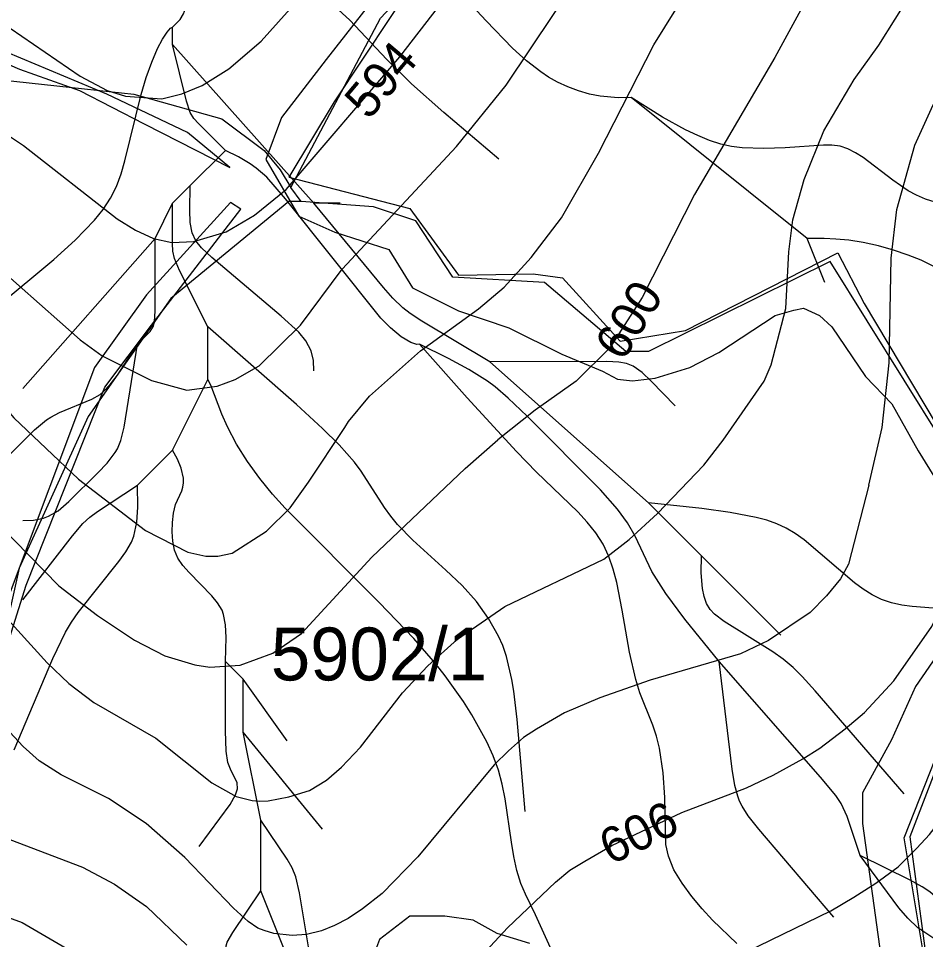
# Model space of a CAD drawing. Extents: x -709584 to -702006, y -1161789 to -1157496.
# Drawn here: x -705935.7 to -705678.4, y -1159835.9 to -1159574.6 of the extents above; entities that cross this region are included whole.
import ezdxf

# ---------------------------------------------------------------- set-up
doc = ezdxf.new("R2010")
doc.units = 0
for name, color, linetype in [('102_obvod PÚ', 7, 'Continuous'), ('120_vrstevnice hlavní', 7, 'Continuous'), ('121_vrstevnice hlavní_popis', 7, 'Continuous'), ('122_vrstevnice základní', 7, 'Continuous'), ('408_BPEJ_linie', 7, 'Continuous'), ('411_akumulovaný odtok', 7, 'Continuous'), ('419_LPIS PB', 7, 'Continuous'), ('419_LPIS PB_kod', 7, 'Continuous')]:
    doc.layers.add(name, color=color, linetype=linetype)

msp = doc.modelspace()

# ---------------------------------------------------------------- linework, layer by layer
at = {"layer": '102_obvod PÚ'}
msp.add_lwpolyline([(-705822.03, -1159561.79), (-705846.15, -1159598.18), (-705859.01, -1159619.55), (-705824.72, -1159628.51), (-705810.91, -1159647.42), (-705789.7, -1159647), (-705781.42, -1159648.14), (-705765.06, -1159666.07), (-705746.55, -1159663.11), (-705703.3, -1159641.06), (-705695.88, -1159655.44), (-705675.44, -1159689.62), (-705663.02, -1159711.13), (-705656.63, -1159738.39), (-705682.88, -1159806.7), (-705674.33, -1159870.62)], dxfattribs=at)
at = {"layer": '120_vrstevnice hlavní'}
for points in [[(-705524.12, -1159497.37), (-705538.14, -1159486.07), (-705565.6, -1159468.62), (-705579.33, -1159462.04), (-705588.48, -1159458.61), (-705602.78, -1159456.18), (-705618.23, -1159457.75), (-705633.24, -1159463.62), (-705642.4, -1159468.34), (-705650.83, -1159474.06), (-705658.41, -1159480.35), (-705665.14, -1159487.64), (-705675.43, -1159502.95), (-705684.16, -1159517.53), (-705721.2, -1159585.61), (-705743.94, -1159624.51), (-705758.81, -1159653.68), (-705767.96, -1159667.98), (-705777.54, -1159677.42), (-705789.16, -1159685.72), (-705799.75, -1159694.12)], [(-705977.91, -1159672.33), (-705972.26, -1159679.93), (-705953.66, -1159704.32), (-705945.4, -1159714.02), (-705924.31, -1159735.53), (-705913.33, -1159743.94), (-705902.79, -1159750.92), (-705894.24, -1159755.34), (-705885.69, -1159757.9), (-705881.42, -1159758.61), (-705872.87, -1159758.04), (-705863.6, -1159754.62), (-705855.48, -1159749.07), (-705835.53, -1159727.41), (-705809.03, -1159702.19), (-705799.75, -1159694.12)]]:
    msp.add_lwpolyline(points, dxfattribs=at)
msp.add_open_spline([(-705799.75, -1159694.12), (-705799.75, -1159694.12)], degree=1, dxfattribs=at)
at = {"layer": '122_vrstevnice základní'}
for points in [[(-705954.31, -1159568.3), (-705941.44, -1159575.03), (-705918.27, -1159590.9), (-705910.55, -1159595.05), (-705905.4, -1159596.62), (-705895.1, -1159597.34), (-705889.38, -1159595.91), (-705883.66, -1159593.62), (-705876.08, -1159588.9), (-705866.93, -1159581.03), (-705854.63, -1159567.16), (-705826.17, -1159528.98), (-705814.87, -1159511.81), (-705807.15, -1159497.51), (-705799.14, -1159480.35), (-705793.13, -1159463.19), (-705787.84, -1159443.17), (-705780.41, -1159400.26)], [(-706168.54, -1159411.13), (-706162.11, -1159425.15), (-706160.68, -1159431.15), (-706160.54, -1159439.16), (-706161.96, -1159459.19), (-706163.11, -1159467.19), (-706163.68, -1159483.21), (-706160.82, -1159493.22), (-706157.53, -1159499.23), (-706151.1, -1159507.52), (-706140.94, -1159516.39), (-706129.93, -1159523.83), (-706068.15, -1159558.58), (-706056.14, -1159564.59), (-706033.83, -1159574.03), (-706009.8, -1159581.75), (-705966.9, -1159593.48), (-705944.58, -1159603.77), (-705934.29, -1159610.64), (-705907.69, -1159631.37)], [(-705907.69, -1159631.37), (-705902.54, -1159634.66), (-705897.39, -1159636.95), (-705892.24, -1159638.09), (-705885.95, -1159637.81), (-705876.8, -1159635.09), (-705868.79, -1159630.37), (-705859.78, -1159623.08), (-705827.6, -1159585.47), (-705816.59, -1159571.31), (-705787.41, -1159536.13), (-705780.26, -1159525.26), (-705763.39, -1159493.22), (-705747.08, -1159465.19), (-705735.21, -1159449.46), (-705719.2, -1159432.73), (-705711.76, -1159426.44), (-705695.88, -1159415.71)], [(-705694.56, -1159706.99), (-705690.74, -1159690.58), (-705688.73, -1159672.28), (-705688.16, -1159642.53), (-705686.59, -1159628.8), (-705681.44, -1159610.49), (-705676.29, -1159599.05), (-705668.28, -1159584.89), (-705650.69, -1159561.01), (-705647.12, -1159554.15), (-705643.83, -1159544.99), (-705639.25, -1159526.69), (-705632.82, -1159510.24), (-705627.67, -1159502.23), (-705619.37, -1159494.08), (-705613.37, -1159490.51), (-705603.35, -1159487.07), (-705597.35, -1159486.36), (-705585.33, -1159487.65), (-705576.61, -1159490.79), (-705563.17, -1159497.94), (-705554.87, -1159504.09), (-705543.86, -1159513.96), (-705534.71, -1159523.26)], [(-705952.88, -1159635.09), (-705918.27, -1159665.7), (-705911.98, -1159670.27), (-705897.96, -1159677.28), (-705887.95, -1159680), (-705879.37, -1159678.85), (-705874.22, -1159676.99), (-705867.5, -1159673.13), (-705855.77, -1159661.55), (-705843.9, -1159645.68), (-705811.44, -1159610.92), (-705797.42, -1159593.48), (-705770.39, -1159553)], [(-705741.37, -1159701.26), (-705735.83, -1159694.15), (-705724.2, -1159677.42), (-705722.2, -1159672.85), (-705718.05, -1159656.83), (-705717.19, -1159640.81), (-705716.05, -1159631.66), (-705712.9, -1159620.22), (-705707.33, -1159606.49), (-705698.74, -1159591.9), (-705691.74, -1159582.18), (-705682.44, -1159567.3)], [(-705842.14, -1159688.94), (-705836.18, -1159681.71), (-705821.74, -1159668.84), (-705805.29, -1159656.97), (-705798, -1159650.82), (-705790.27, -1159642.39), (-705781.69, -1159631.09), (-705771.25, -1159612.78), (-705755.52, -1159582.03), (-705749.23, -1159572.02)], [(-705947.18, -1159676.09), (-705937, -1159687.82), (-705918.72, -1159705.28), (-705899.66, -1159719.86), (-705887.69, -1159725.98), (-705882.56, -1159727.12), (-705879.14, -1159727.12), (-705875.15, -1159726.27), (-705865.33, -1159720.04), (-705858.66, -1159713.35), (-705853.44, -1159706.07), (-705843.16, -1159690.6), (-705842.15, -1159688.94)], [(-705977.74, -1159702.19), (-705927.58, -1159757.33), (-705921.46, -1159763.18), (-705914.33, -1159768.59), (-705896.81, -1159778.71), (-705880.85, -1159791.39), (-705874.01, -1159795.24), (-705869.45, -1159796.38), (-705867.32, -1159796.63), (-705864.89, -1159796.52), (-705859.06, -1159795.38), (-705853.2, -1159793.53), (-705848.36, -1159790.68), (-705844.06, -1159786.98), (-705838.67, -1159781.27), (-705826.84, -1159765.88), (-705819.57, -1159758.19), (-705811.17, -1159750.64), (-705797.77, -1159741.37), (-705769.7, -1159727.98), (-705762.51, -1159722.4), (-705754.45, -1159715.01), (-705741.37, -1159701.27)], [(-705694.56, -1159706.99), (-705700.31, -1159729.4), (-705702.53, -1159733.55), (-705706.58, -1159738.38), (-705711.14, -1159743.08), (-705722.96, -1159751.06), (-705730.94, -1159754.77), (-705756.56, -1159762.26), (-705770.84, -1159767.31), (-705780.82, -1159771.58), (-705788.8, -1159776.14), (-705792.49, -1159778.57), (-705796.77, -1159782.27), (-705800.76, -1159786.26), (-705822.42, -1159812.34), (-705832.54, -1159822.74), (-705838.1, -1159827.16), (-705842.25, -1159829.85), (-705846.08, -1159831.86), (-705849.75, -1159833.36), (-705854.06, -1159834.42), (-705858.05, -1159834.71), (-705863.3, -1159834.13), (-705866.03, -1159833.28), (-705867.84, -1159832.61), (-705870.59, -1159830.72), (-705874.74, -1159826.98), (-705888.54, -1159812.62), (-705899.51, -1159802.93), (-705910.2, -1159795.81), (-705923.59, -1159789.11), (-705929.86, -1159785.12), (-705934.42, -1159781.13), (-705950.53, -1159763.75)], [(-705815.3, -1159852.23), (-705797.06, -1159832.57), (-705783.38, -1159819.6), (-705779.3, -1159816.19), (-705775.12, -1159813.62), (-705767.42, -1159809.2), (-705747.61, -1159799.8), (-705729.23, -1159792.81), (-705721.68, -1159789.25), (-705713.24, -1159784.59), (-705708.43, -1159781.56), (-705701.22, -1159776.07), (-705695.75, -1159771.44), (-705687.48, -1159762.46), (-705676.65, -1159747.07), (-705673.07, -1159739.25), (-705671.65, -1159734.12), (-705670.86, -1159720.33), (-705670.17, -1159709.97)], [(-705749.61, -1159849.24), (-705705.29, -1159827.73), (-705698.76, -1159823.83), (-705692.56, -1159819.82), (-705686.2, -1159815.19), (-705680.93, -1159809.92), (-705677.36, -1159806.07), (-705671.38, -1159798.37), (-705665.4, -1159788.11), (-705659.7, -1159775.29), (-705654.99, -1159759.9), (-705650.58, -1159739.38), (-705650.15, -1159728.55), (-705650.55, -1159712.37)], [(-705938.13, -1159807.49), (-705917.61, -1159815.33), (-705908.49, -1159820.17), (-705899.37, -1159826.44), (-705887.97, -1159837.42)], [(-705938.55, -1159829.6), (-705934.71, -1159831), (-705921.03, -1159838.98)]]:
    msp.add_lwpolyline(points, dxfattribs=at)
for points in [[(-705842.15, -1159688.94), (-705842.14, -1159688.94)], [(-705741.37, -1159701.27), (-705741.37, -1159701.26)], [(-705694.56, -1159706.99), (-705694.56, -1159706.99)]]:
    msp.add_open_spline(points, degree=1, dxfattribs=at)
at = {"layer": '408_BPEJ_linie'}
msp.add_line((-705855.5, -1159626.5), (-705858.5, -1159622.5), dxfattribs=at)
for points in [[(-706111, -1159181.5), (-706096, -1159213), (-706094.5, -1159219), (-706079, -1159351), (-706075.5, -1159399), (-706072, -1159448.5), (-706057.5, -1159507), (-706040.5, -1159543), (-706018.5, -1159565.5), (-705987.5, -1159579.5), (-705940.5, -1159592), (-705917, -1159594.5), (-705903, -1159596), (-705878, -1159603), (-705866, -1159612), (-705861.5, -1159617.5), (-705858.5, -1159622.5)], [(-705858.5, -1159622.5), (-705833, -1159574.5), (-705819.5, -1159560), (-705799.5, -1159555.5), (-705792, -1159550), (-705794, -1159520.5), (-705795, -1159504), (-705816, -1159501.5), (-705836, -1159486), (-705829, -1159455)], [(-705855.5, -1159626.5), (-705859, -1159626.5), (-705892.5, -1159654), (-705916, -1159687.5), (-705935.5, -1159730.5), (-705940.5, -1159753), (-705948, -1159793.5), (-705964, -1159830.5), (-705962.63, -1159831.21)], [(-705672.5, -1159879), (-705684.5, -1159807), (-705668.5, -1159766.5), (-705657, -1159738), (-705661, -1159721.5), (-705674, -1159694), (-705705.5, -1159643.5), (-705757, -1159669), (-705763.5, -1159669), (-705786.5, -1159649.5), (-705812.5, -1159648), (-705823, -1159632), (-705835, -1159628), (-705855.5, -1159626.5)]]:
    msp.add_lwpolyline(points, dxfattribs=at)
at = {"layer": '411_akumulovaný odtok'}
for p, q in [((-705891.99, -1159582), (-705891.99, -1159577)), ((-705851.99, -1159627), (-705891.99, -1159582)), ((-705711.99, -1159637), (-705761.99, -1159597)), ((-705886.99, -1159622), (-705876.99, -1159612)), ((-705891.99, -1159627), (-705886.99, -1159622)), ((-705896.99, -1159637), (-705891.99, -1159627)), ((-705844.49, -1159627), (-705851.99, -1159627)), ((-705934.49, -1159679.5), (-705896.99, -1159637)), ((-705706.99, -1159649.5), (-705711.99, -1159637)), ((-705881.99, -1159677), (-705881.99, -1159662)), ((-705756.99, -1159712), (-705801.99, -1159672)), ((-705891.99, -1159697), (-705881.99, -1159677)), ((-705901.99, -1159707), (-705891.99, -1159697)), ((-705741.99, -1159727), (-705756.99, -1159712)), ((-705719.49, -1159749.5), (-705741.99, -1159727)), ((-705871.99, -1159762), (-705876.99, -1159757)), ((-705871.99, -1159777), (-705871.99, -1159762)), ((-705859.49, -1159779.5), (-705871.99, -1159762)), ((-705866.99, -1159802), (-705871.99, -1159777)), ((-705849.49, -1159804.5), (-705871.99, -1159777)), ((-705866.99, -1159822), (-705866.99, -1159802)), ((-705846.99, -1159872), (-705866.99, -1159822))]:
    msp.add_line(p, q, dxfattribs=at)
for points in [[(-705799.49, -1159614.5), (-705815.04, -1159601.28), (-705824.25, -1159593.11), (-705831.29, -1159586.23), (-705841.7, -1159575.01), (-705846.13, -1159571.07), (-705848.53, -1159569.4), (-705851.15, -1159567.96), (-705853.89, -1159566.73), (-705865.2, -1159562.41), (-705867.91, -1159561.14), (-705870.47, -1159559.66), (-705873.02, -1159557.74), (-705875.39, -1159555.55), (-705879.77, -1159550.62), (-705885.87, -1159542.5), (-705916.99, -1159497)], [(-705761.99, -1159597), (-705765.59, -1159597.05), (-705770.76, -1159596.58), (-705773.74, -1159596.01), (-705776.87, -1159595.12), (-705779.94, -1159593.97), (-705782.83, -1159592.64), (-705785.42, -1159591.2), (-705787.61, -1159589.73), (-705791.63, -1159586.61), (-705795.58, -1159582.99), (-705803.09, -1159575.26), (-705861.99, -1159512)], [(-705891.99, -1159577), (-705889.88, -1159574.87), (-705888.9, -1159573.29), (-705888.65, -1159572.46), (-705888.63, -1159571.56), (-705888.87, -1159570.72), (-705889.3, -1159569.97), (-705891.08, -1159567.94), (-705898.61, -1159560.44), (-705899.84, -1159559.02), (-705900.88, -1159557.52), (-705901.58, -1159555.84), (-705901.91, -1159553.98), (-705902.2, -1159545.09), (-705902.64, -1159542.96), (-705903.09, -1159541.83), (-705904.24, -1159539.98), (-705905.52, -1159538.44), (-705906.99, -1159537)], [(-706024.49, -1159734.5), (-705984.26, -1159694.21), (-705969.66, -1159680.07), (-705957.35, -1159669.21), (-705925.72, -1159642.9), (-705919.69, -1159637.48), (-705914.14, -1159631.8), (-705911.69, -1159628.78), (-705909.58, -1159625.58), (-705907.92, -1159622.22), (-705906.59, -1159618.67), (-705905.52, -1159614.98), (-705900.88, -1159596.18), (-705899.46, -1159591.35), (-705897.92, -1159586.93), (-705896.3, -1159583.13), (-705894.86, -1159580.45), (-705893.57, -1159578.49), (-705892.57, -1159577.31), (-705891.99, -1159577)], [(-705876.99, -1159612), (-705884.66, -1159604.41), (-705885.96, -1159602.91), (-705886.98, -1159601.24), (-705888.03, -1159598.03), (-705891.99, -1159582)], [(-705619.49, -1159632), (-705661.3, -1159628.91), (-705670.08, -1159627.81), (-705675.72, -1159626.64), (-705678.42, -1159625.81), (-705681.02, -1159624.74), (-705683.35, -1159623.48), (-705687.76, -1159620.43), (-705696.17, -1159613.99), (-705698.29, -1159612.64), (-705700.47, -1159611.55), (-705702.71, -1159610.8), (-705705.02, -1159610.48), (-705707.41, -1159610.47), (-705718.3, -1159611.3), (-705724.36, -1159611.45), (-705730.45, -1159611.23), (-705733.47, -1159610.89), (-705736.54, -1159610.27), (-705739.72, -1159609.23), (-705743.08, -1159607.81), (-705746.5, -1159606.15), (-705753.06, -1159602.53), (-705761.99, -1159597)], [(-705821.99, -1159667), (-705822.72, -1159667.03), (-705824.39, -1159666.53), (-705827.2, -1159664.87), (-705830.2, -1159662.35), (-705832.9, -1159659.56), (-705859.96, -1159625.73), (-705865.25, -1159619.58), (-705868.27, -1159616.99), (-705869.98, -1159615.81), (-705873.34, -1159613.82), (-705876.99, -1159612)], [(-705851.99, -1159674.5), (-705852.09, -1159671.57), (-705852.73, -1159668.89), (-705854.21, -1159665.98), (-705856.17, -1159663.55), (-705861.21, -1159659.05), (-705880.9, -1159642.34), (-705883.78, -1159639.6), (-705885.4, -1159637.63), (-705886.49, -1159635.41), (-705887.01, -1159632.47), (-705887.16, -1159628.93), (-705886.99, -1159622)], [(-705881.99, -1159662), (-705890.03, -1159646.02), (-705891.47, -1159642.63), (-705891.91, -1159640.56), (-705892.04, -1159638.45), (-705891.99, -1159627)], [(-705801.99, -1159672), (-705821.35, -1159660.47), (-705824.64, -1159658.28), (-705826.71, -1159656.68), (-705829.55, -1159653.87), (-705832.2, -1159650.85), (-705851.99, -1159627)], [(-705901.99, -1159667), (-705898.36, -1159663.36), (-705897.4, -1159661.83), (-705897.11, -1159660.67), (-705896.94, -1159657.54), (-705896.99, -1159637)], [(-705667.32, -1159649.25), (-705679.73, -1159643.17), (-705683.42, -1159641.69), (-705687.49, -1159640.29), (-705691.77, -1159639.07), (-705696.1, -1159638.12), (-705700.16, -1159637.5), (-705703.91, -1159637.14), (-705707.16, -1159636.97), (-705711.99, -1159637)], [(-705791.99, -1159799.5), (-705794.25, -1159773.39), (-705795.22, -1159765.39), (-705795.78, -1159762.05), (-705797.3, -1159755.57), (-705798.37, -1159752.45), (-705799.55, -1159749.8), (-705802.42, -1159744.74), (-705805.84, -1159739.99), (-705809.89, -1159735.44), (-705814.47, -1159731.08), (-705823.83, -1159722.58), (-705828.18, -1159718.11), (-705830.14, -1159715.73), (-705831.91, -1159713.26), (-705838.48, -1159702.99), (-705840.45, -1159700.42), (-705844.8, -1159695.55), (-705849.48, -1159690.9), (-705856.86, -1159684.1), (-705881.99, -1159662)], [(-705959.49, -1159707), (-705954.5, -1159707.08), (-705951.03, -1159706.8), (-705947.72, -1159706.03), (-705946.24, -1159705.36), (-705945.03, -1159704.56), (-705941.74, -1159701.72), (-705931.17, -1159691.27), (-705927.79, -1159688.46), (-705926.58, -1159687.65), (-705924.1, -1159686.34), (-705914.95, -1159682.58), (-705912.59, -1159681.2), (-705911.57, -1159680.37), (-705909.69, -1159678.41), (-705907.66, -1159675.72), (-705901.99, -1159667)], [(-705934.49, -1159717), (-705931.46, -1159716.92), (-705928.67, -1159716.32), (-705927.2, -1159715.75), (-705924.5, -1159714.2), (-705921.47, -1159711.59), (-705913.22, -1159703.45), (-705910.59, -1159700.67), (-705908.28, -1159697.72), (-705907.67, -1159696.66), (-705906.72, -1159694.31), (-705905.79, -1159690.54), (-705901.99, -1159667)], [(-705736.99, -1159757), (-705746.69, -1159744.93), (-705752.15, -1159737.66), (-705756.04, -1159731.47), (-705760.85, -1159721.47), (-705762.99, -1159717.62), (-705765.82, -1159713.73), (-705770.65, -1159708.27), (-705791.48, -1159687.37), (-705796.81, -1159682.3), (-705800.5, -1159679.09), (-705802.68, -1159677.46), (-705808.03, -1159674.12), (-705813.72, -1159671.05), (-705821.99, -1159667)], [(-705731.99, -1159837), (-705738.88, -1159830.35), (-705741.82, -1159827.17), (-705744.78, -1159823.64), (-705747.52, -1159819.89), (-705749.81, -1159816.03), (-705751.4, -1159812.2), (-705752.09, -1159808.87), (-705752.39, -1159795.57), (-705752.85, -1159788.52), (-705753.9, -1159781.55), (-705754.77, -1159778.17), (-705755.84, -1159775.07), (-705759.47, -1159765.83), (-705760.62, -1159762.09), (-705762.38, -1159754.32), (-705764.47, -1159742.41), (-705766.03, -1159734.58), (-705767.03, -1159730.8), (-705768.28, -1159727.15), (-705769.88, -1159723.7), (-705771.95, -1159720.47), (-705774.39, -1159717.43), (-705777.08, -1159714.53), (-705788.76, -1159703.26), (-705794.48, -1159697.42), (-705808.45, -1159682.23), (-705821.99, -1159667)], [(-705749.49, -1159684.5), (-705756.3, -1159677.41), (-705758.82, -1159675.03), (-705761.38, -1159673.2), (-705763.31, -1159672.44), (-705765.45, -1159672.08), (-705768.8, -1159671.91), (-705801.99, -1159672)], [(-705783.45, -1159841.3), (-705789.05, -1159828.88), (-705791.95, -1159822.98), (-705793.21, -1159819.96), (-705794.36, -1159816.22), (-705795.21, -1159812.31), (-705795.87, -1159808.27), (-705797.68, -1159795.9), (-705798.5, -1159791.8), (-705799.6, -1159787.77), (-705801.09, -1159783.73), (-705802.9, -1159779.78), (-705807.16, -1159772.1), (-705809.54, -1159768.35), (-705814.67, -1159761.05), (-705817.42, -1159757.53), (-705823.59, -1159750.43), (-705833.4, -1159740.23), (-705860.11, -1159713.49), (-705863.64, -1159709.52), (-705867.25, -1159705.04), (-705870.73, -1159700.24), (-705873.86, -1159695.31), (-705876.46, -1159690.45), (-705878.07, -1159686.78), (-705881.12, -1159678.6), (-705881.99, -1159677)], [(-705876.99, -1159757), (-705876.85, -1159750.15), (-705877.02, -1159746.61), (-705877.53, -1159743.6), (-705877.98, -1159742.41), (-705879.27, -1159740.29), (-705880.91, -1159738.32), (-705887.35, -1159731.69), (-705889.06, -1159729.73), (-705890.51, -1159727.67), (-705891.48, -1159725.37), (-705891.94, -1159722.84), (-705892.1, -1159720.21), (-705892.05, -1159717.55), (-705891.78, -1159714.94), (-705891.2, -1159712.45), (-705889.41, -1159708.58), (-705889.06, -1159707.52), (-705888.88, -1159706.34), (-705888.94, -1159704.98), (-705889.61, -1159702.17), (-705890.64, -1159699.61), (-705891.99, -1159697)], [(-705936.99, -1159782), (-705925.97, -1159756.09), (-705922.41, -1159748.66), (-705920.7, -1159745.82), (-705918.76, -1159743.09), (-705907.26, -1159728.57), (-705905.31, -1159725.89), (-705903.64, -1159723.1), (-705902.97, -1159721.44), (-705902.17, -1159717.45), (-705901.9, -1159713.2), (-705901.99, -1159707)], [(-705934.49, -1159739.5), (-705920.4, -1159721.33), (-705917.44, -1159717.85), (-705915.44, -1159716.06), (-705913.27, -1159714.47), (-705901.99, -1159707)], [(-705666.78, -1159742.63), (-705682.21, -1159741.41), (-705685.2, -1159740.96), (-705688.11, -1159740.31), (-705690.9, -1159739.37), (-705693.57, -1159738.06), (-705696.12, -1159736.47), (-705698.58, -1159734.66), (-705712.88, -1159722.5), (-705715.39, -1159720.7), (-705718.01, -1159719.14), (-705720.67, -1159717.91), (-705723.46, -1159716.92), (-705726.46, -1159716.1), (-705733.83, -1159714.7), (-705741.94, -1159713.6), (-705756.99, -1159712)], [(-705684.49, -1159794.5), (-705709.72, -1159765.28), (-705713.43, -1159761.22), (-705716.03, -1159758.66), (-705718.81, -1159756.34), (-705721.78, -1159754.27), (-705735.6, -1159745.64), (-705738.32, -1159743.55), (-705739.52, -1159742.23), (-705740.53, -1159740.56), (-705741.27, -1159738.52), (-705741.74, -1159736.3), (-705742.1, -1159731.87), (-705741.99, -1159727)], [(-705884.49, -1159809.5), (-705875.72, -1159797.55), (-705874.16, -1159794.84), (-705873.59, -1159793.06), (-705873.69, -1159791.41), (-705875.63, -1159787.51), (-705876.32, -1159785.65), (-705876.83, -1159782.39), (-705877.03, -1159776.67), (-705876.99, -1159757)], [(-705696.99, -1159812), (-705700.66, -1159800.97), (-705702.42, -1159797.25), (-705703.91, -1159795.03), (-705708.22, -1159789.8), (-705736.99, -1159757)], [(-705704.49, -1159829.5), (-705725.78, -1159804.57), (-705728.76, -1159800.73), (-705730.46, -1159798.05), (-705731.17, -1159796.64), (-705731.72, -1159795.2), (-705732.53, -1159792.18), (-705733.34, -1159787.47), (-705736.99, -1159757)], [(-705851.99, -1159847), (-705856, -1159822.61), (-705857.03, -1159818.02), (-705858.12, -1159815.46), (-705859.55, -1159813.03), (-705866.99, -1159802)], [(-705639.49, -1159842), (-705646.3, -1159842.19), (-705651.51, -1159842.14), (-705654.22, -1159841.82), (-705656.61, -1159841.11), (-705658.77, -1159839.82), (-705660.78, -1159838.18), (-705673.19, -1159825.84), (-705677.23, -1159822.35), (-705679.4, -1159820.92), (-705682.82, -1159819), (-705696.99, -1159812)], [(-705644.49, -1159854.5), (-705675, -1159836.28), (-705680.63, -1159832.5), (-705683.48, -1159829.81), (-705686, -1159826.81), (-705696.99, -1159812)], [(-705876.99, -1159847), (-705877.02, -1159839.22), (-705876.83, -1159837.61), (-705876.52, -1159836.6), (-705874.91, -1159833.81), (-705866.99, -1159822)]]:
    msp.add_lwpolyline(points, dxfattribs=at)
at = {"layer": '419_LPIS PB'}
for points in [[(-705820.33, -1159550.24), (-705848.46, -1159586.23), (-705861.08, -1159602.65), (-705865.53, -1159614.57), (-705856.22, -1159630.61), (-705845.96, -1159635.2), (-705830.68, -1159640.11), (-705823.93, -1159651.01), (-705810.92, -1159657.54), (-705796.65, -1159662.3), (-705781.63, -1159669.83), (-705770.11, -1159674.6), (-705765.86, -1159676.86), (-705761.61, -1159677.36), (-705755.1, -1159676.61), (-705745.34, -1159673.59), (-705737.07, -1159669.33), (-705721.06, -1159658.79), (-705715.8, -1159657.29), (-705713.05, -1159656.78), (-705708.54, -1159658.79), (-705705.04, -1159662.05), (-705695.52, -1159676.11), (-705688.01, -1159683.88), (-705680.51, -1159697.18), (-705672.87, -1159709.65)], [(-705994.66, -1159563.22), (-705935.39, -1159588.97), (-705918.46, -1159594.97), (-705900.11, -1159604.49), (-705875.79, -1159616.84), (-705887.77, -1159606.96), (-705910.7, -1159596.03), (-705955.5, -1159577.33)], [(-705959.41, -1159817.52), (-705933.52, -1159735.28), (-705911.19, -1159679.15), (-705898, -1159661.6), (-705872.7, -1159628.7), (-705875.6, -1159626.8), (-705899.4, -1159653), (-705914.2, -1159673.6), (-705965.45, -1159810.13)], [(-705674.59, -1159754.32), (-705681.34, -1159764.11), (-705688.1, -1159779.17), (-705696.36, -1159794.23), (-705696.36, -1159802.9), (-705691.11, -1159840.55)], [(-705790.73, -1159836.93), (-705799.91, -1159834.13), (-705806.71, -1159830.36), (-705814.76, -1159829.21), (-705824.7, -1159829.26), (-705833.3, -1159835.8), (-705835.6, -1159841.9)]]:
    msp.add_lwpolyline(points, dxfattribs=at)

# ---------------------------------------------------------------- texts
at = {"layer": '121_vrstevnice hlavní_popis'}
for s, rotation, p in [('594', 49.8738, (-705836.36, -1159603.64)), ('600', 58.3385, (-705764.22, -1159672.14)), ('606', 25.4914, (-705767.78, -1159814.8))]:
    msp.add_text(s, height=10, rotation=rotation, dxfattribs=at).set_placement(p)
at = {"layer": '419_LPIS PB_kod'}
msp.add_text('5902/1', height=15, dxfattribs=at).set_placement((-705864.14, -1159762.35))

doc.saveas('drawing.dxf')
